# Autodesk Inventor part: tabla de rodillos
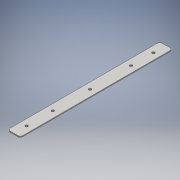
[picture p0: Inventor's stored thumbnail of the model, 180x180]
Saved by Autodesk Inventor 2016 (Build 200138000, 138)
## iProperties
Created: 2016-06
Part Number: tabla de rodillos
Material: Genérico
Document SubType Name: Modeling
Designer: adm
Density: 1 g/cm^3
Appearance: Valor por defecto
Author: adm
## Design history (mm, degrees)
sketch "Boceto1"
  geometry: L1 (-25, -300)-(25, -300); L2 (25, -300)-(25, 300); L3 (25, 300)-(-25, 300); L4 (-25, 300)-(-25, -300); L5 (-25, -300)-(25, 300); L6 (25, -300)-(-25, 300); C1 r 5 at (0, 250); C2 r 5 at (0, -250); 3 further points
  constraints: 12 end point, 2 centre point, 2 coincident, 2 midpoint, 2 parallel, 1 horizontal, 1 perpendicular
  dimensions: "d0" = 50 distance of L3.end L2.end; "d1" = 600 distance of L2.end L1.end; "d2" = 50 distance from line of point (0, 250) L3; "d3" = 10 diameter of C1; "d4" = 50 distance from line of L1 point (0, -250); "d5" = 10 diameter of C2
extrude "Extrusión1" new body sketch "Boceto1" distance "d6" = 4; taper "d7" = 0 deg
fillet "Empalme1" dims "d8" = 10
sketch "Boceto2"
  geometry: C1 r 5 at (0, 162.025); C2 r 5 at (0, 0); C3 r 5 at (0, -146.872); 4 further points
  constraints: 4 coincident, 3 centre point
  dimensions: "d9" = 10 diameter of C1; "d10" = 10 diameter of C2; "d11" = 10 diameter of C3
extrude "Extrusión2" cut sketch "Boceto2" distance "d12" = 10; taper "d13" = 0 deg
node "Sólido1"
